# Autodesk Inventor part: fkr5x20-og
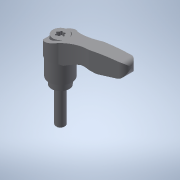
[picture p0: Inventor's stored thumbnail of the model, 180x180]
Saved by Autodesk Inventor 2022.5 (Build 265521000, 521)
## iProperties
Created: 2017-09
Part Number: fkr5x20-og
Material: 一般
Document SubType Name: Modeling
Designer: imaocorp
Density: 1 g/cm^3
Appearance: 既定
Author: imaocorp
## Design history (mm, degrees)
node "fkr5x20-og.x_t1"
node "fkr5x20-og"
node "Base1"
